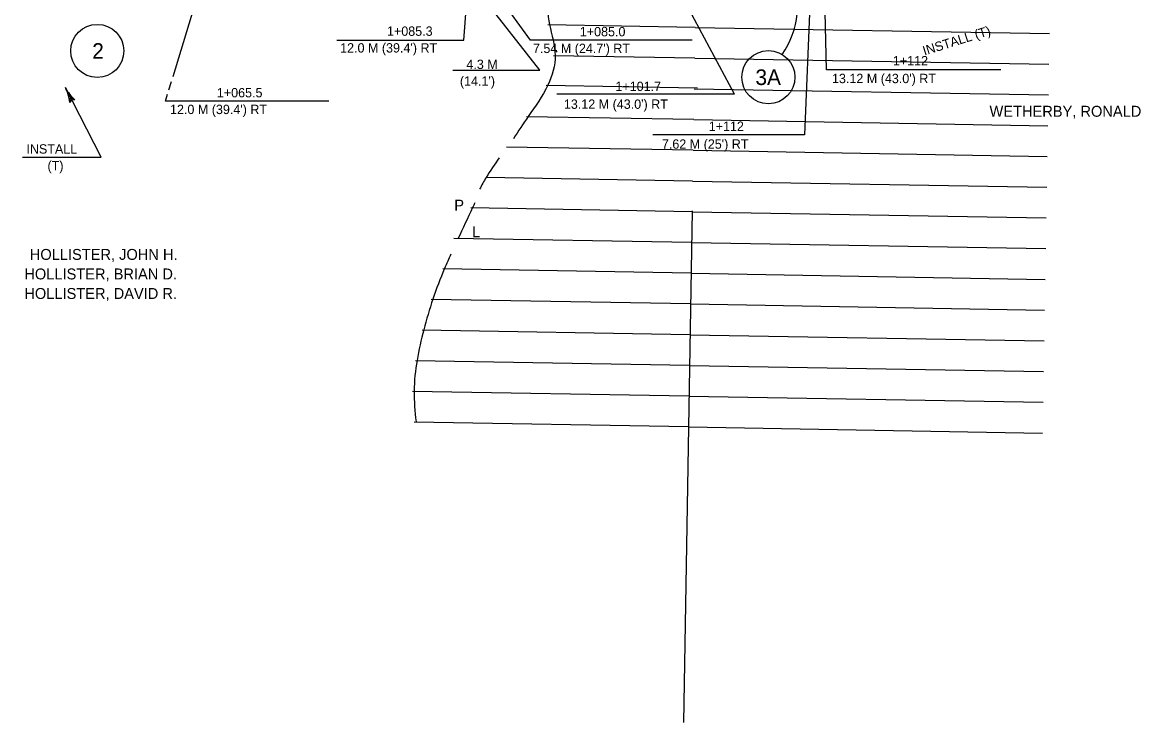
# Model space of a CAD drawing. Extents: x 435838 to 436160, y 121991 to 122158.
# Drawn here: x 435970.5 to 436061.5, y 121991.1 to 122048.1 of the extents above; entities that cross this region are included whole.
import ezdxf

# ---------------------------------------------------------------- set-up
doc = ezdxf.new("R2010")
doc.units = 0
for name, color, linetype in [('Level 16', 7, 'Continuous'), ('Level 3', 7, 'Continuous'), ('Level 37', 7, 'Continuous'), ('Level 38', 7, 'Continuous'), ('Level 4', 7, 'Continuous'), ('Level 5', 7, 'Continuous'), ('Level 7', 7, 'Continuous')]:
    doc.layers.add(name, color=color, linetype=linetype)

msp = doc.modelspace()

# ---------------------------------------------------------------- linework, layer by layer
at = {"layer": 'Level 16'}
for p, q in [((435974.444, 122041.702), (435974.429, 122041.911)), ((435974.678, 122041.822), (435974.516, 122041.956)), ((435974.408, 122041.556), (435974.57, 122041.745)), ((435974.817, 122041.765), (435974.569, 122041.745))]:
    msp.add_line(p, q, dxfattribs=at)
for centre, start, end in [((435977.093272, 122044.318977), 207.13266707, 228.35591985), ((435971.006369, 122041.198013), 5.93562538, 27.15887815)]:
    msp.add_arc(centre, 3.420733, start, end, dxfattribs=at)
at = {"layer": 'Level 3'}
for p, q in [((436035.964, 122044.208), (436035.819, 122050.457)), ((436028.482, 122042.218), (436024.821, 122049.059)), ((436050.163, 122044.208), (436035.964, 122044.208))]:
    msp.add_line(p, q, dxfattribs=at)
for points in [[(436015.063, 122057.872), (436015.062, 122057.869), (436014.018, 122055.387), (436013.325, 122052.899), (436013.182, 122050.4), (436013.438, 122047.896), (436013.895, 122045.388), (436013.31, 122042.961), (436011.708, 122040.425), (436010.5, 122038.607)], [(436009.342, 122037.046), (436008.283, 122035.454), (436007.745, 122034.501)], [(436007.354, 122033.382), (436007.179, 122033.002), (436005.978, 122030.451)], [(436005.417, 122029.225), (436004.892, 122028.041), (436003.949, 122025.556), (436003.205, 122023.069), (436002.662, 122020.578), (436002.419, 122018.081), (436002.575, 122015.579)]]:
    msp.add_spline(points, degree=3, dxfattribs=at)
at = {"layer": 'Level 37'}
for p, q in [((436013.299, 122047.869), (436013.299, 122047.869)), ((436013.756, 122045.361), (436013.756, 122045.361)), ((436013.171, 122042.934), (436013.171, 122042.934)), ((436011.569, 122040.398), (436011.569, 122040.398)), ((436009.926, 122037.925), (436009.926, 122037.925)), ((436008.283, 122035.454), (436008.283, 122035.454)), ((436007.04, 122032.975), (436007.04, 122032.975)), ((436005.647, 122030.498), (436005.647, 122030.498)), ((436004.753, 122028.014), (436004.753, 122028.014)), ((436003.81, 122025.529), (436003.81, 122025.529)), ((436003.066, 122023.042), (436003.066, 122023.042)), ((436002.523, 122020.551), (436002.523, 122020.551)), ((436002.28, 122018.054), (436002.28, 122018.054)), ((436002.436, 122015.552), (436002.436, 122015.552))]:
    msp.add_line(p, q, dxfattribs=at)
at = {"layer": 'Level 38'}
for p, q in [((436025.297, 122047.662), (436013.299, 122047.869)), ((436025.297, 122047.662), (436054.111, 122047.162)), ((436025.254, 122045.162), (436013.756, 122045.361)), ((436025.254, 122045.162), (436054.068, 122044.662)), ((436025.469, 122042.722), (436013.171, 122042.934)), ((436025.21, 122042.663), (436054.024, 122042.163)), ((436025.167, 122040.163), (436011.569, 122040.398)), ((436025.167, 122040.163), (436053.981, 122039.663)), ((436025.124, 122037.663), (436009.926, 122037.925)), ((436025.124, 122037.663), (436053.938, 122037.163)), ((436025.08, 122035.164), (436008.283, 122035.454)), ((436025.08, 122035.164), (436053.894, 122034.664)), ((436025.037, 122032.664), (436007.04, 122032.975)), ((436025.046, 122032.728), (436024.326, 121991.108)), ((436025.037, 122032.664), (436053.851, 122032.164)), ((436024.994, 122030.164), (436005.647, 122030.498)), ((436024.994, 122030.164), (436053.808, 122029.664)), ((436024.95, 122027.665), (436004.753, 122028.014)), ((436024.95, 122027.665), (436053.764, 122027.165)), ((436024.907, 122025.165), (436003.81, 122025.529)), ((436024.907, 122025.165), (436053.721, 122024.665)), ((436024.863, 122022.666), (436003.066, 122023.042)), ((436024.863, 122022.666), (436053.677, 122022.166)), ((436024.82, 122020.166), (436002.523, 122020.551)), ((436024.82, 122020.166), (436053.634, 122019.666)), ((436024.777, 122017.666), (436002.28, 122018.054)), ((436024.777, 122017.666), (436053.591, 122017.166)), ((436024.733, 122015.167), (436002.436, 122015.552)), ((436024.733, 122015.167), (436053.547, 122014.667))]:
    msp.add_line(p, q, dxfattribs=at)
at = {"layer": 'Level 5'}
for p, q in [((436011.899, 122046.629), (436006.723, 122053.738)), ((435982.807, 122043.675), (435985.1, 122051.164)), ((436034.707, 122051.664), (436034.194, 122038.922)), ((436006.471, 122046.633), (436006.677, 122049.465)), ((435996.129, 122046.633), (436006.471, 122046.633)), ((436025.029, 122046.629), (436011.899, 122046.629)), ((436014.062, 122045.646), (436013.819, 122045.916)), ((435982.468, 122042.569), (435982.677, 122043.25)), ((435982.191, 122041.665), (435982.363, 122042.228)), ((436028.482, 122042.218), (436014.027, 122042.218)), ((435995.494, 122041.665), (435982.191, 122041.665)), ((436034.194, 122038.922), (436021.848, 122038.922))]:
    msp.add_line(p, q, dxfattribs=at)
for centre in [(435976.646, 122045.744), (436031.24, 122043.61)]:
    msp.add_circle(centre, 2.16, dxfattribs=at)
msp.add_arc((436026.777595, 122049.417149), 6.836392, 324.64157466, 24.20419966, dxfattribs=at)
at = {"layer": 'Level 7'}
for p, q in [((436012.647, 122044.187), (436006.6, 122051.911)), ((436005.571, 122044.187), (436012.647, 122044.187)), ((435976.948, 122037.105), (435974.049, 122042.759)), ((435970.548, 122037.105), (435976.948, 122037.105))]:
    msp.add_line(p, q, dxfattribs=at)

# ---------------------------------------------------------------- texts
at = {"layer": 'Level 3'}
for s, p in [('P', (436005.689, 122032.756)), ('L', (436007.133, 122030.588))]:
    msp.add_text(s, height=0.889002, dxfattribs=at).set_placement(p)
at = {"layer": 'Level 4'}
for s, p in [('WETHERBY, RONALD', (436049.234, 122040.393)), ('HOLLISTER, JOHN H.', (435971.153, 122028.75)), ('HOLLISTER, BRIAN D.', (435970.709, 122027.161)), ('HOLLISTER, DAVID R.', (435970.709, 122025.572))]:
    msp.add_text(s, height=0.889002, dxfattribs=at).set_placement(p)
at = {"layer": 'Level 5'}
for s, height, p in [('1+085.3', 0.761874, (436000.214, 122046.975)), ('1+085.0', 0.761874, (436015.902, 122046.935)), ('2', 1.270002, (435976.232, 122045.109)), ("12.0 M (39.4') RT", 0.761874, (435996.401, 122045.614)), ("7.54 M (24.7') RT", 0.761874, (436012.089, 122045.574)), ('1+112', 0.761874, (436041.374, 122044.572)), ('3A', 1.270002, (436030.19, 122042.975)), ("13.12 M (43.0') RT", 0.761874, (436036.418, 122043.125)), ('1+065.5', 0.761874, (435986.373, 122041.971)), ('1+101.7', 0.761874, (436018.799, 122042.484)), ("13.12 M (43.0') RT", 0.761874, (436014.605, 122041.037)), ("12.0 M (39.4') RT", 0.761874, (435982.56, 122040.61)), ('1+112', 0.761874, (436026.391, 122039.239)), ("7.62 M (25') RT", 0.761874, (436022.579, 122037.792))]:
    msp.add_text(s, height=height, dxfattribs=at).set_placement(p)
at = {"layer": 'Level 7'}
msp.add_text('INSTALL (T)', height=0.761868, rotation=17.3689202, dxfattribs=at).set_placement((436043.938, 122045.367))
for s, p in [('4.3 M', (436006.675, 122044.277)), ("(14.1')", (436006.147, 122042.915)), ('INSTALL', (435970.878, 122037.394)), ('(T)', (435972.592, 122036.032))]:
    msp.add_text(s, height=0.761874, dxfattribs=at).set_placement(p)

doc.saveas('drawing.dxf')
